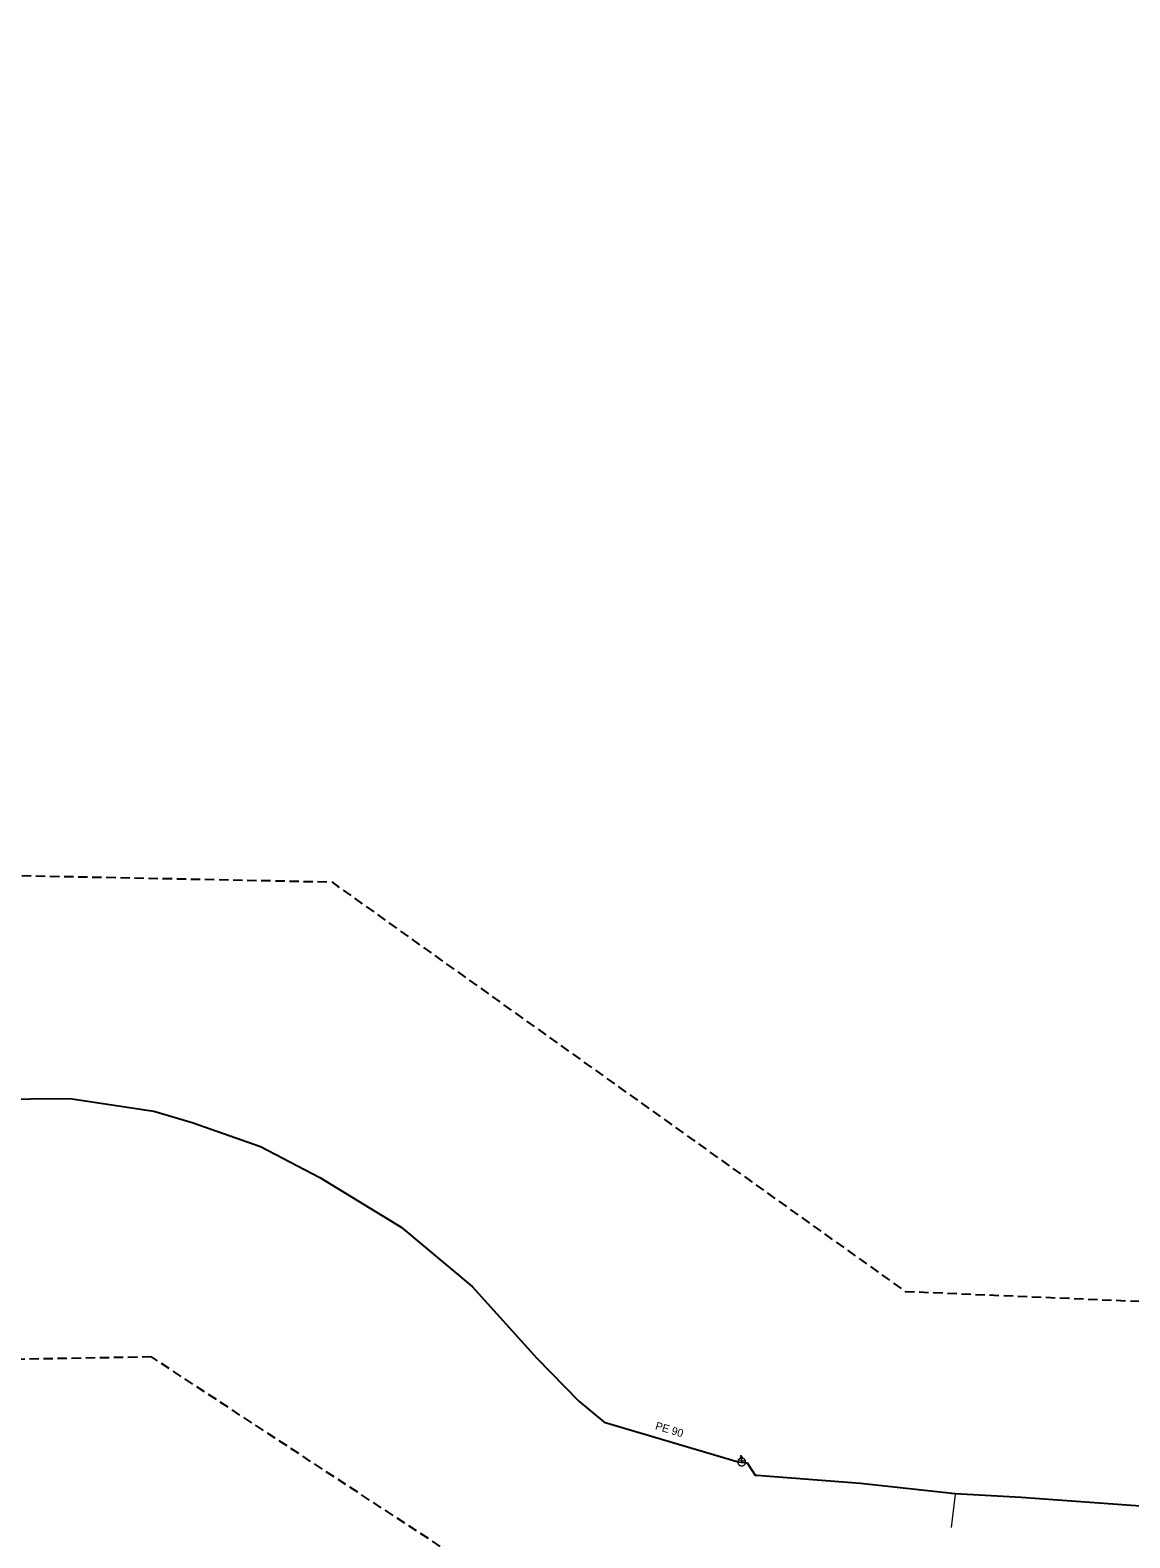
# Model space of a CAD drawing. Extents: x -692311 to -690519, y -971696 to -970899.
# Drawn here: x -691277.8 to -691137.3, y -971307 to -971114.3 of the extents above; entities that cross this region are included whole.
import ezdxf

# ---------------------------------------------------------------- set-up
doc = ezdxf.new("R2010")
doc.units = 0
doc.header["$LTSCALE"] = 0.4
doc.linetypes.add('MEDIUM_DASHED', pattern=[4.5, 3, -1.5])
for name, color, linetype, lineweight in [('1', 7, 'MEDIUM_DASHED', 25), ('13', 7, 'Continuous', 13), ('14', 7, 'Continuous', 13), ('17', 7, 'Continuous', 25), ('34', 7, 'Continuous', 13), ('47', 7, 'Continuous', 13), ('9', 7, 'Continuous', 13)]:
    doc.layers.add(name, color=color, linetype=linetype, lineweight=lineweight)

msp = doc.modelspace()

# ---------------------------------------------------------------- linework, layer by layer
at = {"layer": '1'}
msp.add_lwpolyline([(-691582.607, -971118.48), (-691415.135, -971114.294), (-691341.865, -971221.058), (-691239.288, -971223.151), (-691166.019, -971275.486), (-690967.145, -971283.86), (-690879.221, -971315.261), (-690772.457, -971417.838), (-690699.188, -971434.585), (-690602.891, -971597.872), (-690519.155, -971629.273), (-690531.715, -971696.262), (-690636.386, -971646.02), (-690749.43, -971493.201), (-690789.205, -971468.08), (-690914.809, -971369.69), (-690979.705, -971342.475), (-691195.326, -971327.822), (-691262.316, -971283.86), (-691377.453, -971285.953), (-691463.283, -971177.096)], dxfattribs=at)
at = {"layer": '13'}
msp.add_line((-691159.64, -971301.401), (-691160.149, -971305.68), dxfattribs=at)
at = {"layer": '14'}
msp.add_line((-691159.629, -971301.3), (-691159.64, -971301.401), dxfattribs=at)
msp.add_lwpolyline([(-691186.899, -971297.289), (-691186.87, -971297.07), (-691186.93, -971296.73)], dxfattribs=at)
at = {"layer": '17'}
for points in [[(-691290.219, -971250.469), (-691283.579, -971250.239), (-691282.82, -971250.93), (-691272.739, -971250.84), (-691262.02, -971252.43), (-691257.1, -971253.91), (-691248.399, -971256.96), (-691240.809, -971260.91), (-691230.43, -971267.27), (-691221.359, -971274.879), (-691213.079, -971284), (-691207.69, -971289.53), (-691204.469, -971292.199), (-691187.35, -971297.28), (-691186.899, -971297.289)], [(-691186.899, -971297.289), (-691186.195, -971297.397), (-691185.18, -971298.96), (-691184.98, -971298.989), (-691171.739, -971299.989), (-691159.629, -971301.3), (-691151.21, -971301.78), (-691123.09, -971303.809)]]:
    msp.add_lwpolyline(points, dxfattribs=at)
at = {"layer": '34'}
for p, q in [((-691187.365, -971297.002), (-691186.374, -971297.138)), ((-691159.142, -971301.451), (-691160.137, -971301.349))]:
    msp.add_line(p, q, dxfattribs=at)
at = {"layer": '47'}
for points in [[(-691186.404, -971297.364), (-691186.399, -971297.312), (-691186.399, -971297.26), (-691186.406, -971297.208), (-691186.416, -971297.157), (-691186.433, -971297.107), (-691186.455, -971297.059), (-691186.481, -971297.015), (-691186.512, -971296.972), (-691186.547, -971296.934), (-691186.586, -971296.898), (-691186.629, -971296.868), (-691186.674, -971296.842), (-691186.722, -971296.821), (-691186.772, -971296.805), (-691186.823, -971296.794), (-691186.875, -971296.789), (-691186.927, -971296.789), (-691186.98, -971296.796), (-691187.03, -971296.806), (-691187.08, -971296.823), (-691187.128, -971296.845), (-691187.173, -971296.871), (-691187.216, -971296.902), (-691187.254, -971296.937), (-691187.289, -971296.976), (-691187.319, -971297.019), (-691187.346, -971297.064), (-691187.366, -971297.112), (-691187.382, -971297.162), (-691187.393, -971297.213), (-691187.398, -971297.265), (-691187.398, -971297.317), (-691187.392, -971297.37), (-691187.381, -971297.42), (-691187.364, -971297.47), (-691187.343, -971297.518), (-691187.317, -971297.563), (-691187.286, -971297.605), (-691187.25, -971297.644), (-691187.211, -971297.679), (-691187.168, -971297.709), (-691187.124, -971297.736), (-691187.075, -971297.756), (-691187.025, -971297.772), (-691186.974, -971297.783), (-691186.922, -971297.788), (-691186.87, -971297.788), (-691186.818, -971297.782), (-691186.767, -971297.771), (-691186.717, -971297.754), (-691186.669, -971297.733), (-691186.625, -971297.707), (-691186.583, -971297.676), (-691186.544, -971297.64), (-691186.508, -971297.601), (-691186.478, -971297.558), (-691186.452, -971297.514), (-691186.431, -971297.465), (-691186.415, -971297.415)], [(-691186.817, -971297.301), (-691186.816, -971297.292), (-691186.817, -971297.284), (-691186.818, -971297.276), (-691186.819, -971297.267), (-691186.822, -971297.259), (-691186.826, -971297.251), (-691186.83, -971297.243), (-691186.835, -971297.237), (-691186.841, -971297.231), (-691186.847, -971297.225), (-691186.855, -971297.219), (-691186.862, -971297.215), (-691186.87, -971297.212), (-691186.877, -971297.209), (-691186.886, -971297.207), (-691186.895, -971297.206), (-691186.903, -971297.207), (-691186.911, -971297.208), (-691186.92, -971297.209), (-691186.928, -971297.212), (-691186.936, -971297.216), (-691186.944, -971297.22), (-691186.95, -971297.225), (-691186.957, -971297.231), (-691186.962, -971297.237), (-691186.968, -971297.245), (-691186.972, -971297.252), (-691186.975, -971297.26), (-691186.978, -971297.267), (-691186.98, -971297.276), (-691186.981, -971297.285), (-691186.98, -971297.293), (-691186.979, -971297.301), (-691186.978, -971297.31), (-691186.975, -971297.318), (-691186.972, -971297.326), (-691186.967, -971297.334), (-691186.962, -971297.34), (-691186.956, -971297.347), (-691186.95, -971297.352), (-691186.942, -971297.358), (-691186.935, -971297.362), (-691186.927, -971297.365), (-691186.92, -971297.368), (-691186.911, -971297.37), (-691186.902, -971297.371), (-691186.894, -971297.37), (-691186.886, -971297.369), (-691186.877, -971297.368), (-691186.869, -971297.365), (-691186.861, -971297.362), (-691186.853, -971297.357), (-691186.847, -971297.352), (-691186.841, -971297.346), (-691186.835, -971297.34), (-691186.829, -971297.332), (-691186.825, -971297.325), (-691186.822, -971297.317), (-691186.819, -971297.31)]]:
    msp.add_lwpolyline(points, close=True, dxfattribs=at)
at = {"layer": '9'}
for points in [[(-691187.056, -971296.524), (-691187.103, -971296.509), (-691187.06, -971296.493)], [(-691186.93, -971296.603), (-691186.93, -971296.511), (-691187.103, -971296.509)]]:
    msp.add_lwpolyline(points, dxfattribs=at)
for points in [[(-691187.057, -971296.729), (-691187.056, -971296.742), (-691187.054, -971296.755), (-691187.051, -971296.768), (-691187.046, -971296.78), (-691187.04, -971296.792), (-691187.033, -971296.803), (-691187.025, -971296.813), (-691187.015, -971296.823), (-691187.005, -971296.831), (-691186.994, -971296.838), (-691186.982, -971296.844), (-691186.97, -971296.849), (-691186.957, -971296.852), (-691186.944, -971296.854), (-691186.931, -971296.857), (-691186.918, -971296.856), (-691186.905, -971296.854), (-691186.892, -971296.851), (-691186.88, -971296.846), (-691186.868, -971296.84), (-691186.857, -971296.833), (-691186.847, -971296.825), (-691186.837, -971296.815), (-691186.829, -971296.805), (-691186.822, -971296.794), (-691186.816, -971296.782), (-691186.811, -971296.77), (-691186.808, -971296.757), (-691186.806, -971296.744), (-691186.804, -971296.731), (-691186.805, -971296.718), (-691186.807, -971296.705), (-691186.81, -971296.692), (-691186.815, -971296.68), (-691186.821, -971296.668), (-691186.828, -971296.657), (-691186.836, -971296.647), (-691186.846, -971296.637), (-691186.856, -971296.629), (-691186.867, -971296.622), (-691186.879, -971296.616), (-691186.891, -971296.611), (-691186.904, -971296.608), (-691186.917, -971296.606), (-691186.93, -971296.603), (-691186.943, -971296.604), (-691186.956, -971296.606), (-691186.969, -971296.609), (-691186.981, -971296.614), (-691186.993, -971296.62), (-691187.004, -971296.627), (-691187.014, -971296.635), (-691187.024, -971296.645), (-691187.032, -971296.655), (-691187.039, -971296.666), (-691187.045, -971296.678), (-691187.05, -971296.69), (-691187.053, -971296.703), (-691187.055, -971296.716)], [(-691187.037, -971296.729), (-691187.037, -971296.74), (-691187.035, -971296.751), (-691187.032, -971296.762), (-691187.028, -971296.772), (-691187.023, -971296.782), (-691187.017, -971296.791), (-691187.01, -971296.8), (-691187.002, -971296.808), (-691186.993, -971296.815), (-691186.984, -971296.821), (-691186.974, -971296.826), (-691186.964, -971296.83), (-691186.953, -971296.833), (-691186.942, -971296.835), (-691186.931, -971296.837), (-691186.92, -971296.837), (-691186.909, -971296.835), (-691186.898, -971296.832), (-691186.888, -971296.828), (-691186.878, -971296.823), (-691186.869, -971296.817), (-691186.86, -971296.81), (-691186.852, -971296.802), (-691186.845, -971296.793), (-691186.839, -971296.784), (-691186.834, -971296.774), (-691186.83, -971296.764), (-691186.827, -971296.753), (-691186.825, -971296.742), (-691186.824, -971296.731), (-691186.824, -971296.72), (-691186.826, -971296.709), (-691186.829, -971296.698), (-691186.833, -971296.688), (-691186.838, -971296.678), (-691186.844, -971296.669), (-691186.851, -971296.66), (-691186.859, -971296.652), (-691186.868, -971296.645), (-691186.877, -971296.639), (-691186.887, -971296.634), (-691186.897, -971296.63), (-691186.908, -971296.627), (-691186.919, -971296.625), (-691186.93, -971296.624), (-691186.941, -971296.623), (-691186.952, -971296.625), (-691186.963, -971296.628), (-691186.973, -971296.632), (-691186.983, -971296.637), (-691186.992, -971296.643), (-691187.001, -971296.65), (-691187.009, -971296.658), (-691187.016, -971296.667), (-691187.022, -971296.676), (-691187.027, -971296.686), (-691187.031, -971296.696), (-691187.034, -971296.707), (-691187.036, -971296.718)], [(-691187.018, -971296.729), (-691187.017, -971296.738), (-691187.016, -971296.747), (-691187.013, -971296.756), (-691187.01, -971296.764), (-691187.006, -971296.772), (-691187.001, -971296.78), (-691186.995, -971296.787), (-691186.989, -971296.793), (-691186.982, -971296.799), (-691186.974, -971296.804), (-691186.966, -971296.808), (-691186.958, -971296.811), (-691186.949, -971296.814), (-691186.94, -971296.815), (-691186.931, -971296.818), (-691186.922, -971296.817), (-691186.913, -971296.816), (-691186.904, -971296.813), (-691186.896, -971296.81), (-691186.888, -971296.806), (-691186.88, -971296.801), (-691186.873, -971296.795), (-691186.867, -971296.789), (-691186.861, -971296.782), (-691186.856, -971296.774), (-691186.852, -971296.766), (-691186.849, -971296.758), (-691186.846, -971296.749), (-691186.845, -971296.74), (-691186.843, -971296.731), (-691186.844, -971296.722), (-691186.845, -971296.713), (-691186.848, -971296.704), (-691186.851, -971296.696), (-691186.855, -971296.688), (-691186.86, -971296.68), (-691186.866, -971296.673), (-691186.872, -971296.667), (-691186.879, -971296.661), (-691186.887, -971296.656), (-691186.895, -971296.652), (-691186.903, -971296.649), (-691186.912, -971296.646), (-691186.921, -971296.645), (-691186.93, -971296.642), (-691186.939, -971296.643), (-691186.948, -971296.644), (-691186.957, -971296.647), (-691186.965, -971296.65), (-691186.973, -971296.654), (-691186.981, -971296.659), (-691186.988, -971296.665), (-691186.994, -971296.671), (-691187, -971296.678), (-691187.005, -971296.686), (-691187.009, -971296.694), (-691187.012, -971296.702), (-691187.015, -971296.711), (-691187.016, -971296.72)], [(-691186.998, -971296.729), (-691186.998, -971296.736), (-691186.996, -971296.743), (-691186.995, -971296.75), (-691186.992, -971296.756), (-691186.989, -971296.762), (-691186.985, -971296.768), (-691186.981, -971296.774), (-691186.976, -971296.779), (-691186.97, -971296.783), (-691186.964, -971296.787), (-691186.958, -971296.79), (-691186.952, -971296.793), (-691186.945, -971296.794), (-691186.938, -971296.796), (-691186.931, -971296.798), (-691186.924, -971296.798), (-691186.917, -971296.796), (-691186.91, -971296.795), (-691186.904, -971296.792), (-691186.897, -971296.789), (-691186.892, -971296.785), (-691186.886, -971296.781), (-691186.881, -971296.776), (-691186.877, -971296.77), (-691186.873, -971296.764), (-691186.87, -971296.758), (-691186.867, -971296.752), (-691186.865, -971296.745), (-691186.864, -971296.738), (-691186.863, -971296.731), (-691186.863, -971296.724), (-691186.864, -971296.717), (-691186.866, -971296.71), (-691186.869, -971296.704), (-691186.872, -971296.697), (-691186.876, -971296.692), (-691186.88, -971296.686), (-691186.885, -971296.681), (-691186.891, -971296.677), (-691186.896, -971296.673), (-691186.903, -971296.67), (-691186.909, -971296.667), (-691186.916, -971296.665), (-691186.923, -971296.664), (-691186.93, -971296.663), (-691186.937, -971296.662), (-691186.944, -971296.663), (-691186.951, -971296.665), (-691186.957, -971296.668), (-691186.963, -971296.671), (-691186.969, -971296.675), (-691186.975, -971296.679), (-691186.98, -971296.684), (-691186.984, -971296.69), (-691186.988, -971296.695), (-691186.991, -971296.702), (-691186.994, -971296.708), (-691186.995, -971296.715), (-691186.997, -971296.722)], [(-691186.978, -971296.729), (-691186.978, -971296.734), (-691186.977, -971296.739), (-691186.976, -971296.744), (-691186.974, -971296.748), (-691186.972, -971296.753), (-691186.969, -971296.757), (-691186.966, -971296.76), (-691186.962, -971296.764), (-691186.959, -971296.767), (-691186.955, -971296.77), (-691186.95, -971296.772), (-691186.946, -971296.774), (-691186.941, -971296.775), (-691186.936, -971296.776), (-691186.931, -971296.777), (-691186.926, -971296.778), (-691186.921, -971296.777), (-691186.916, -971296.776), (-691186.912, -971296.774), (-691186.907, -971296.772), (-691186.903, -971296.769), (-691186.899, -971296.766), (-691186.896, -971296.762), (-691186.893, -971296.759), (-691186.89, -971296.755), (-691186.888, -971296.75), (-691186.886, -971296.746), (-691186.885, -971296.741), (-691186.884, -971296.736), (-691186.883, -971296.731), (-691186.883, -971296.726), (-691186.884, -971296.721), (-691186.885, -971296.716), (-691186.887, -971296.712), (-691186.889, -971296.707), (-691186.892, -971296.703), (-691186.895, -971296.699), (-691186.898, -971296.696), (-691186.902, -971296.693), (-691186.906, -971296.69), (-691186.911, -971296.688), (-691186.915, -971296.686), (-691186.92, -971296.685), (-691186.925, -971296.684), (-691186.93, -971296.683), (-691186.935, -971296.682), (-691186.94, -971296.683), (-691186.945, -971296.684), (-691186.949, -971296.686), (-691186.954, -971296.688), (-691186.958, -971296.691), (-691186.961, -971296.694), (-691186.965, -971296.697), (-691186.968, -971296.701), (-691186.971, -971296.705), (-691186.973, -971296.71), (-691186.975, -971296.714), (-691186.976, -971296.719), (-691186.977, -971296.724)], [(-691186.958, -971296.729), (-691186.958, -971296.732), (-691186.958, -971296.735), (-691186.957, -971296.737), (-691186.956, -971296.74), (-691186.955, -971296.743), (-691186.953, -971296.745), (-691186.951, -971296.747), (-691186.949, -971296.749), (-691186.947, -971296.751), (-691186.945, -971296.753), (-691186.942, -971296.754), (-691186.939, -971296.755), (-691186.937, -971296.756), (-691186.934, -971296.756), (-691186.931, -971296.756), (-691186.928, -971296.758), (-691186.925, -971296.758), (-691186.922, -971296.757), (-691186.92, -971296.756), (-691186.917, -971296.755), (-691186.915, -971296.753), (-691186.912, -971296.751), (-691186.91, -971296.749), (-691186.909, -971296.747), (-691186.907, -971296.745), (-691186.906, -971296.742), (-691186.905, -971296.739), (-691186.904, -971296.737), (-691186.904, -971296.734), (-691186.902, -971296.731), (-691186.903, -971296.728), (-691186.903, -971296.725), (-691186.904, -971296.722), (-691186.905, -971296.72), (-691186.906, -971296.717), (-691186.908, -971296.715), (-691186.909, -971296.712), (-691186.911, -971296.71), (-691186.914, -971296.709), (-691186.916, -971296.707), (-691186.919, -971296.706), (-691186.921, -971296.705), (-691186.924, -971296.704), (-691186.927, -971296.704), (-691186.93, -971296.701), (-691186.933, -971296.702), (-691186.936, -971296.702), (-691186.938, -971296.703), (-691186.941, -971296.704), (-691186.944, -971296.705), (-691186.946, -971296.707), (-691186.948, -971296.708), (-691186.95, -971296.71), (-691186.952, -971296.713), (-691186.954, -971296.715), (-691186.955, -971296.718), (-691186.956, -971296.72), (-691186.957, -971296.723), (-691186.957, -971296.726)], [(-691186.939, -971296.729), (-691186.939, -971296.73), (-691186.939, -971296.731), (-691186.938, -971296.731), (-691186.938, -971296.732), (-691186.938, -971296.733), (-691186.937, -971296.734), (-691186.937, -971296.734), (-691186.936, -971296.735), (-691186.936, -971296.735), (-691186.935, -971296.736), (-691186.934, -971296.736), (-691186.933, -971296.736), (-691186.933, -971296.737), (-691186.932, -971296.737), (-691186.931, -971296.739), (-691186.93, -971296.739), (-691186.929, -971296.739), (-691186.929, -971296.738), (-691186.928, -971296.738), (-691186.927, -971296.738), (-691186.926, -971296.737), (-691186.926, -971296.737), (-691186.925, -971296.736), (-691186.925, -971296.736), (-691186.924, -971296.735), (-691186.924, -971296.734), (-691186.923, -971296.733), (-691186.923, -971296.733), (-691186.923, -971296.732), (-691186.922, -971296.731), (-691186.922, -971296.73), (-691186.922, -971296.729), (-691186.922, -971296.729), (-691186.923, -971296.728), (-691186.923, -971296.727), (-691186.924, -971296.726), (-691186.924, -971296.726), (-691186.925, -971296.725), (-691186.925, -971296.725), (-691186.926, -971296.724), (-691186.927, -971296.724), (-691186.928, -971296.723), (-691186.928, -971296.723), (-691186.929, -971296.723), (-691186.93, -971296.722), (-691186.931, -971296.722), (-691186.932, -971296.721), (-691186.932, -971296.721), (-691186.933, -971296.722), (-691186.934, -971296.722), (-691186.935, -971296.723), (-691186.935, -971296.723), (-691186.936, -971296.724), (-691186.936, -971296.724), (-691186.937, -971296.725), (-691186.937, -971296.726), (-691186.937, -971296.727), (-691186.938, -971296.727), (-691186.938, -971296.728)]]:
    msp.add_lwpolyline(points, close=True, dxfattribs=at)

# ---------------------------------------------------------------- texts
at = {"layer": '1'}
msp.add_text('PE 90 ', height=1, rotation=343, dxfattribs=at).set_placement((-691198.025, -971293.084))

doc.saveas('drawing.dxf')
